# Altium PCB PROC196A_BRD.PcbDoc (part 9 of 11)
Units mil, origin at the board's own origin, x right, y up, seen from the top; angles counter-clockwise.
Board outline 3346.45 x 4921.26 mil, 8 copper layers (Top Layer, GND1, SIG1, PWR1, PWR2, SIG2, GND2, Bottom Layer), stack 54.534 mil thick; 736 components, 498 nets, 3030 pads, 1279 vias.
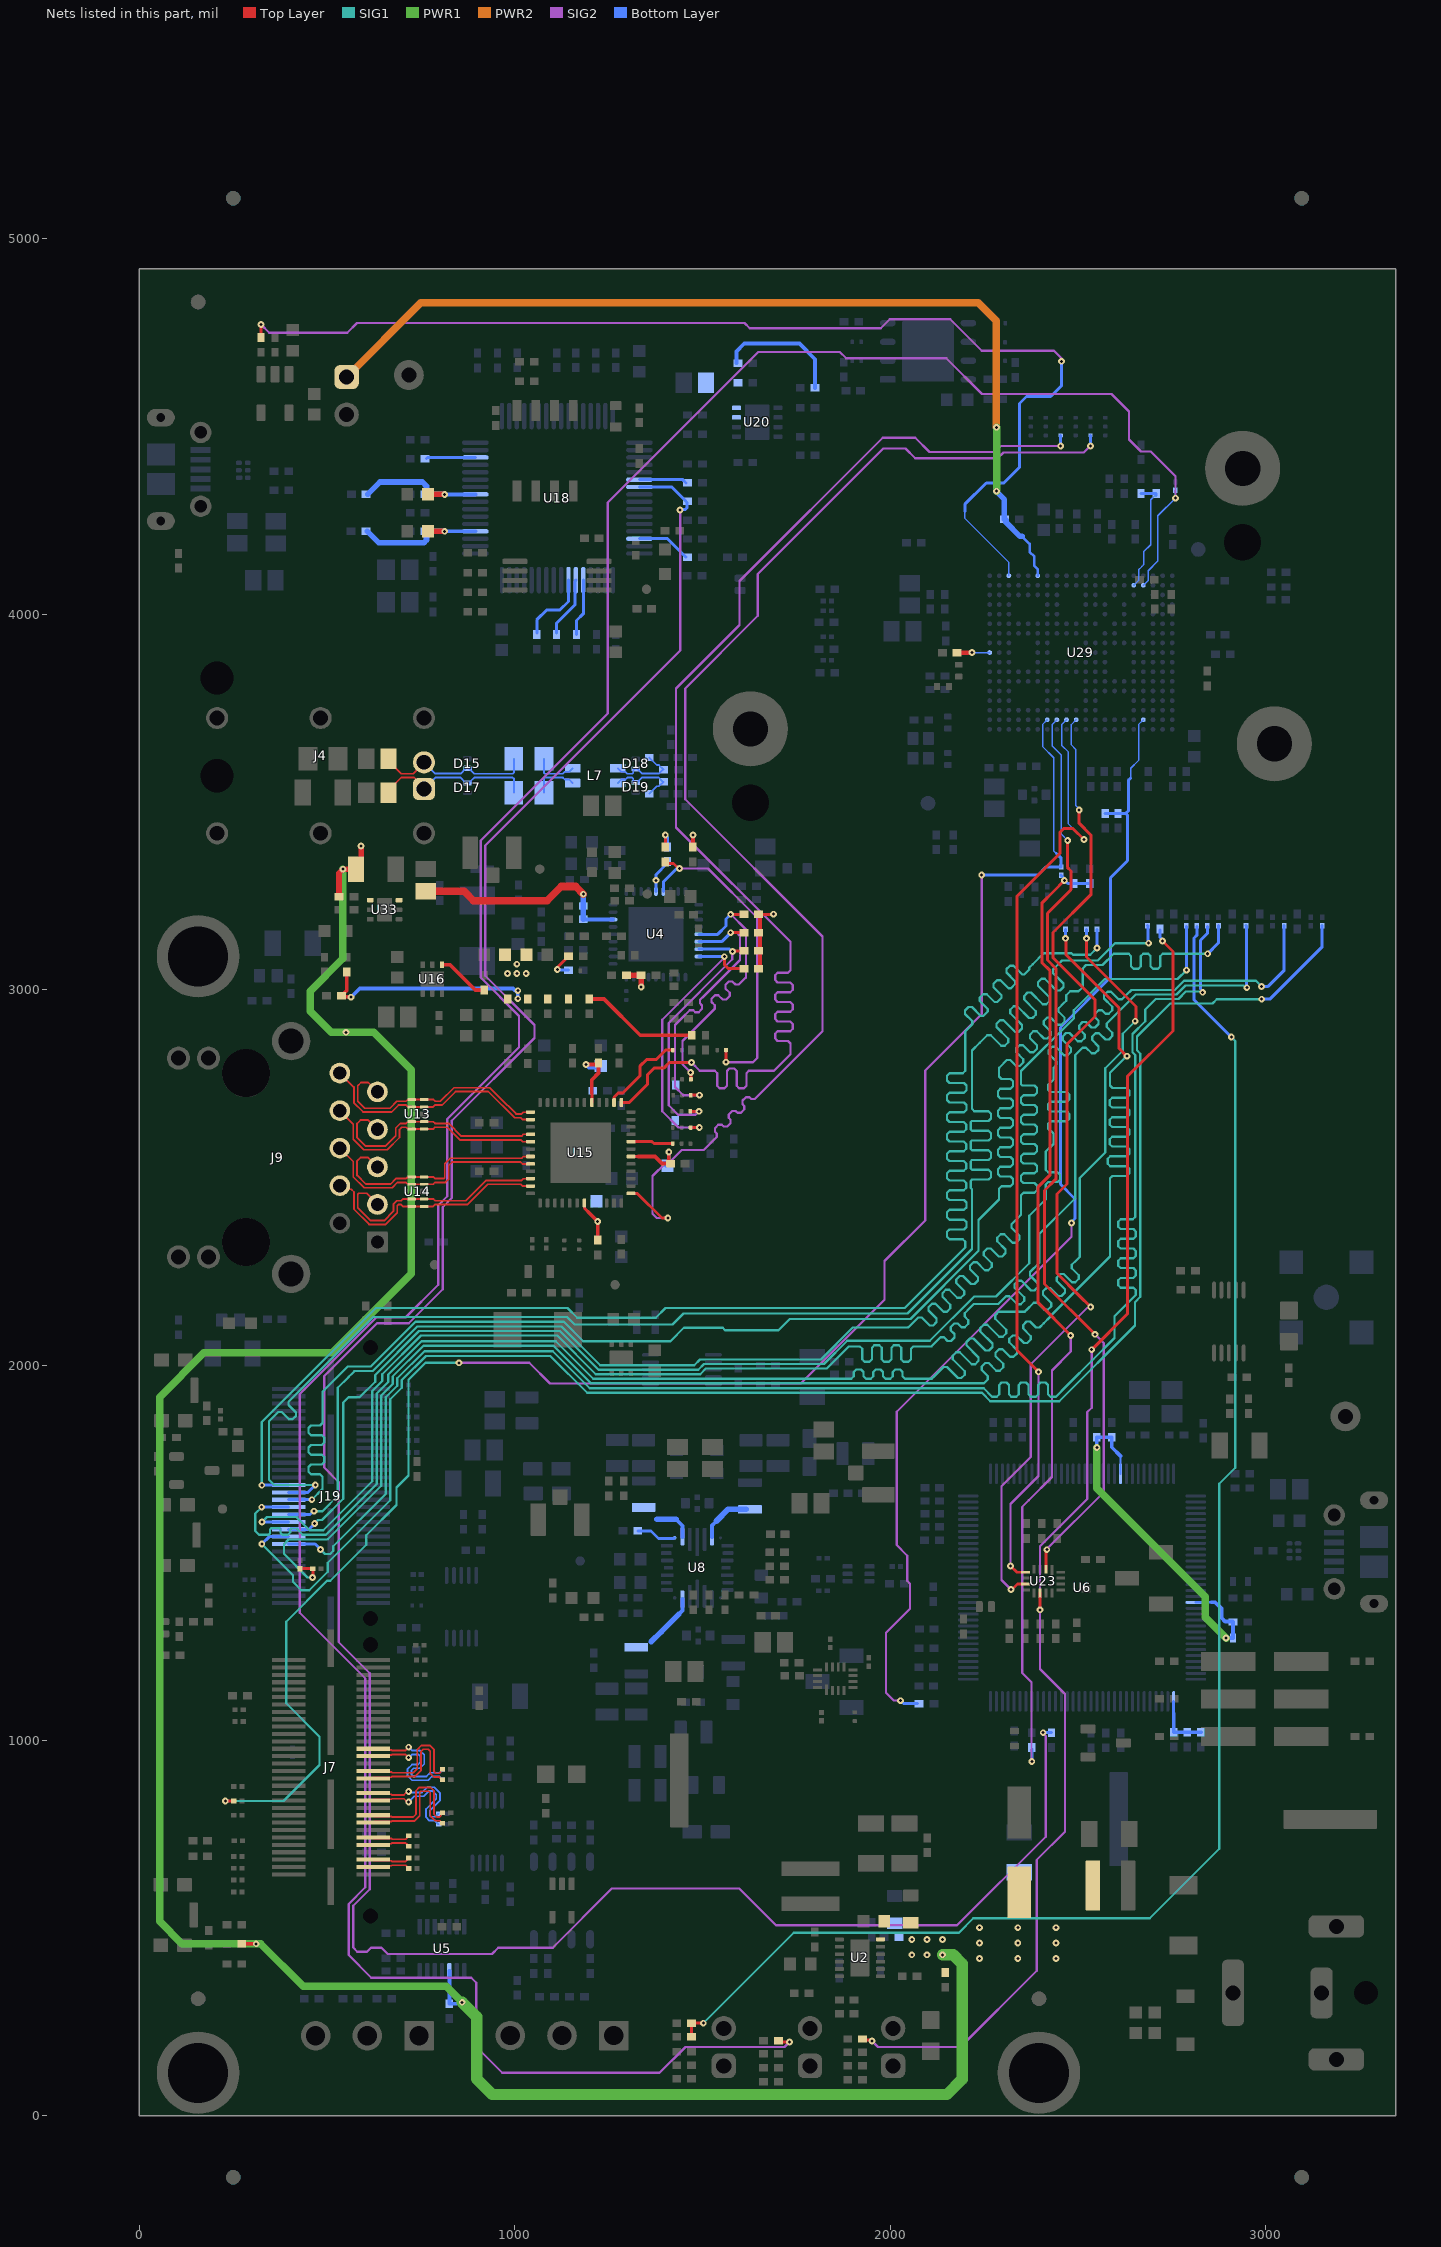
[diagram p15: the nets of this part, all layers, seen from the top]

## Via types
v1: diameter 18, hole 8, Top Layer to Bottom Layer, tented both sides, 1230 vias
v2: diameter 19.68, hole 7.87, Top Layer to Bottom Layer, 30 vias
v3: diameter 20, hole 10, Top Layer to Bottom Layer, tented both sides, 11 vias
v4: diameter 10, hole 4, SIG2 to Bottom Layer, tented both sides, 6 vias
v5: diameter 19.68, hole 7.87, Top Layer to Bottom Layer, tented both sides, 2 vias

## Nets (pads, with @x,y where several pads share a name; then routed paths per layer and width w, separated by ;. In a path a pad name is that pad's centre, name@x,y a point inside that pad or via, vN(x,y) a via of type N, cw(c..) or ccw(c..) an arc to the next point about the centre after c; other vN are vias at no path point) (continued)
RGMII_TD3: R122.2 U15.25 | length 3484.7
  Top Layer w8: U15.25@1309.79,2457.27 1326.6,2457.27 1392.29,2391.59 v1(1407.8,2391.59)
  SIG2 w6: v1(1407.8,2391.59) 1378.54,2391.59 1367,2403.13 1367,2503.47 1402.72,2539.19 1411.26,2539.19 1444.88,2572.81 1503.28,2572.81 1533.64,2603.17 1538.24,2607.77 1538.24,2616.96 1533.29,2621.91 1533.29,2631.1 1542.48,2640.29 1551.67,2640.29 1556.62,2635.34 1565.81,2635.34 1575.01,2644.53 1575.01,2653.73 1570.06,2658.68 1570.06,2667.87 1579.25,2677.06 1588.44,2677.06 1593.39,2672.11 1602.58,2672.11 1611.78,2681.3 1611.78,2690.5 1606.83,2695.45 1606.83,2704.64 1616.02,2713.83 1625.21,2713.83 1630.16,2708.88 1639.35,2708.88 1653.14,2722.67 1671.53,2741.06 1820,2889.53 1820,3141.76 1454.28,3507.48 1454.28,3802.59 1647.68,3995.99 1647.68,4107.4 1982.09,4441.81 2040.97,4441.81 2066.97,4415.81 2286.92,4415.81 2302.11,4431 2515.96,4431 v1(2533.79,4448.83)
  Bottom Layer w8: v1(2533.79,4448.83) R122.2@2533.81,4476.69
RST_FTDI: R163.2 U18.14 | length 131.3
  Bottom Layer w8: R163.2@765.07,4415.03 767.99,4417.95 U18.14@895.17,4417.95
RX_CLK: R290.2 U15.32 | length 113.2
  Top Layer w8: U15.32@1309.79,2595.07 1365.91,2595.07 1370.95,2590.02 R290.2@1420.91,2590.02
RX_CTRL: R195.2 U15.38 | length 238.1
  Top Layer w8: U15.38@1264.51,2699.4 1264.51,2713.47 1275.25,2724.21 1287.3,2724.21 1334.33,2771.24 1334.33,2797.14 1351.5,2814.31 1377.16,2814.31 1402.14,2839.29 R195.2@1421.22,2839.29
RX_D0: R237.2 R255.1 U4.26 | length 761.8
  Top Layer w8: R237.2@1468.46,2632.81 v1@1491.75,2632.81 ; v1(1558.39,3087.85) 1558.39,3067.08 1569.42,3056.06 R255.1@1606.4,3056.06
  SIG2 w6: v1(1491.81,2632.87) 1436.44,2632.87 1393,2676.31 1393,2919.99 1558.39,3085.38 v1(1558.39,3087.85)
  Bottom Layer w8: U4.26@1490.38,3088.51 1490.71,3088.18 1558.06,3088.18 v1(1558.39,3087.85)
RX_D1: R238.2 R256.1 U4.25 | length 718.2
  Top Layer w8: R238.2@1467.74,2676.12 v1@1491.02,2676.12 ; v1(1580.45,3102.05) 1581.4,3102.99 1605.45,3102.99 R256.1@1606.4,3103.94
  SIG2 w6: v1(1491.09,2676.19) 1490.62,2676.19 1481.57,2667.14 1435.17,2667.14 1410,2692.31 1410,2911.64 1579.4,3081.05 1579.4,3101 v1(1580.45,3102.05)
  Bottom Layer w8: U4.25@1490.38,3108.19 1571.68,3108.19 1577.83,3102.05 v1(1580.45,3102.05)
RX_D2: R239.2 R257.1 U4.24 | length 754.5
  Top Layer w8: R239.2@1469.18,2718.89 v1@1492.46,2718.89 ; v1(1575.37,3151.97) R257.1@1606.4,3151.97
  SIG2 w6: v1@1490.08,2716.5 v1@1491.5,2715.07 ; v1(1492.53,2718.95) 1448.86,2718.95 1427,2740.81 1427,2906.27 1445.58,2924.85 1466.08,2945.36 1475.28,2945.36 1480.79,2939.84 1489.98,2939.84 1499.18,2949.03 1499.18,2958.23 1493.66,2963.74 1493.66,2972.94 1504.1,2983.38 1599.88,3079.15 1599.88,3099.89 1599.94,3099.94 1599.94,3114.85 1599.88,3114.91 1599.88,3143.32 1591.23,3151.97 v1(1575.37,3151.97)
  Bottom Layer w8: U4.24@1490.38,3127.88 1551.28,3127.88 v1(1575.37,3151.97)
RX_D3: R240.2 R258.1 U4.23 | length 763
  Top Layer w8: v1(1468.78,2779.77) 1469.11,2779.43 1469.11,2761.42 R240.2@1469.44,2761.09 ; v1(1575.37,3200.99) R258.1@1606.4,3200.99
  SIG2 w6: v1(1468.78,2779.77) 1447,2801.54 1447,2863.63 1530.56,2947.19 1532.69,2949.31 1532.69,2958.5 1524.11,2967.08 1524.11,2976.27 1533.3,2985.47 1542.49,2985.47 1554.12,2973.84 1563.31,2973.84 1572.5,2983.03 1572.5,2992.23 1561.18,3003.55 1561.18,3012.74 1570.37,3021.94 1579.56,3021.94 1587.84,3013.66 1597.03,3013.66 1610.34,3026.97 1616.03,3032.65 1616.03,3160.33 v1(1575.37,3200.99)
  Bottom Layer w8: U4.23@1490.38,3147.56 1540.71,3147.56 1563.06,3169.91 1563.06,3188.68 v1(1575.37,3200.99)
RX_DV: R245.2 R252.1 U4.15 | length 881.8
  Top Layer w8: R245.2@1562.84,2839.29 1562.91,2839.22 1562.91,2806.93 v1(1562.98,2806.86)
  Top Layer w8.3: R252.1@1401.29,3336.43 1422.79,3336.43 1431.14,3328.08 1431.52,3328.08 1436.37,3323.23 v1(1438.99,3323.23)
  SIG2 w6: v1(1438.99,3323.23) 1514.6,3323.23 1645.84,3191.98 1645.84,2817.95 1634.75,2806.86 v1(1562.98,2806.86)
  Bottom Layer w8: U4.15@1395.89,3261.74 1395.89,3287.15 1430.11,3321.37 1437.14,3321.37 v1(1438.99,3323.23)
SOP0_FTDI: R171.1 U18.55 | length 196.5
  Bottom Layer w8: R171.1@1058.91,3950.19 1058.91,3985.33 1085.16,4011.58 1120.24,4011.58 1143.2,4034.54 U18.55@1143.2,4091.18
SOP0_TDO: R310.1 R386.1 U23.10 | length 3595
  Top Layer w7.5: v1(2399.49,1347.9) 2399.58,1347.99 2399.58,1392.88 U23.10@2399.67,1392.97
  Top Layer w8: R310.1@1926.71,204.71 1929.95,201.47 1949.76,201.47 v1(1951.68,199.56) ; v1(2537.07,2041) 2631.98,2135.91 2631.98,2768.53 2753.55,2890.1 2753.55,3101.75 v1(2725.49,3129.81)
  SIG2 w6: v1(1951.68,199.56) 1967.92,183.32 2187.81,183.32 2391,386.5 2391,681.81 2466,756.81 2466,1010.67 2466,1123.92 2399.49,1190.43 v1(2399.49,1347.9) 2399.49,1517.37 2521.93,1639.81 2525.28,1643.16 2525.28,1874.69 2537.07,1886.48 v1(2537.07,2041)
  Bottom Layer w8: R386.1@2719,3159.44 2719,3139.55 2725.49,3133.06 v1(2725.49,3129.81)
SOP1_FTDI: R170.1 U18.54 | length 162.4
  Bottom Layer w8: R170.1@1111.12,3950.19 1111.12,3976.45 1161.12,4026.45 1161.12,4089.42 U18.54@1162.88,4091.18
SOP1_MSS_SPIB_CS2: R305.1 R324.1 U29.T17 | length 8106.6
  Top Layer w8: R305.1@1702.27,199.99 1705.42,196.84 v1(1732.2,196.84)
  SIG2 w6: v1(1732.2,196.84) 1718.96,183.59 1454.95,183.59 1385.92,114.56 966.81,114.56 897.44,183.93 897.44,354.61 884.24,367.81 635.39,367.81 620.47,367.8 618,367.81 557.53,428.28 557.53,564.31 602,608.78 602,1165.35 427,1340.35 427,1922.73 631.22,2126.96 709.25,2126.96 796,2213.71 796,2425.37 820.24,2449.61 820.24,2655.8 1011.33,2846.89 1011.33,2930.27 909.28,3032.32 909.28,3397.28 1248,3736 1248,4297.94 1648.92,4698.86 1866,4698.86 1882.86,4682 2149.53,4682 2244.72,4586.81 2590,4586.81 2636.5,4540.31 2636.5,4465.81 2668.5,4433.81 2694.49,4433.81 2760.08,4368.22 v1(2760.08,4309.55)
  Bottom Layer w4: U29.T17@2674.75,4077.38 2687.47,4090.1 2687.47,4097.65 2687.51,4097.69 2687.51,4108.26 2687.47,4108.29 2687.47,4116.03 2713.31,4141.87 2713.31,4262.78 v1(2760.08,4309.55) ; v1@2759.85,4309.55 R324.1@2759.85,4330.39
SOP2_FTDI: R169.1 U18.53 | length 152.4
  Bottom Layer w8: R169.1@1164.49,3946.25 1164.49,3983.49 1182.57,4001.57 U18.53@1182.57,4091.18
SOP2_PMIC_CLK: R218.2 R297.1 R299.1 | length 4157.5
  Top Layer w8: R299.1@1471.02,210.44 R297.1@1471.02,246.66 v1(1502.46,246.66)
  SIG1 w6: v1(1502.46,246.66) 1743.64,487.84 2161.97,487.84 ; 2162,487.81 2183.47,487.81 2221.84,526.18 2691.83,526.18 2877.17,711.52 2877.17,1684.09 2919.5,1726.43 2919.5,2863.31 v1(2909,2873.81)
  Bottom Layer w8: R218.2@2817.15,3168.1 2817.15,3144.83 2809.82,3137.5 2809.82,2972.99 v1(2909,2873.81)
SOP3_MSS_GPIO_0: R212.1 R328.1 U29.B7 | length 4795.3
  Top Layer w8: v1(229,838.88) R328.1@251.34,838.88
  SIG1 w6: v1(229,838.88) 384.07,838.88 480,934.81 480,1009.81 391,1098.81 391,1316.13 500.1,1425.23 508.47,1425.23 604.23,1521 604.23,1546.36 685,1627.13 685,1674.12 716.99,1706.11 716.99,1960.77 762.17,2005.95 v1(851.82,2005.95)
  SIG2 w6: v1(851.82,2005.95) 1038.71,2005.95 1093.86,1950.8 1761.77,1950.8 1985.17,2174.2 1985.17,2276.96 2093.57,2385.36 2093.57,2784.84 2244,2935.27 2244,3261.81 v1(2244,3305.81)
  Bottom Layer w4: U29.B7@2418.84,3719.11 2406.12,3706.39 2406.12,3648.17 2436.13,3618.17 2436.13,3369.86 2443.6,3362.38
  Bottom Layer w8: v1(2244,3305.81) 2393.75,3305.81 2414.98,3327.04 R212.1@2455.7,3327.04 2455.7,3350.29 2443.6,3362.38
SOP3_MSS_UARTB_TX: R136.1 R212.2 R301.1 R303.2 | length 2616.2
  Top Layer w8: v1(2464.23,3290.81) 2435.23,3261.81 2404.11,3230.69 2404.11,3072.71 2426.4,3050.43 2426.4,2506.84 2394.34,2474.78 2394.34,2165.75 v1(2481.09,2079)
  SIG2 w6: v1(2377.63,944.16) 2376.98,944.8 2376.98,1154.83 2351.93,1179.88 2351.93,1389.31 2352,1389.38 2352,1414.24 2351.93,1414.31 2351.93,1622.23 2369.5,1639.81 2431.31,1701.61 2431.31,1985.73 2481.51,2035.93 2481.51,2078.58 v1(2481.09,2079)
  Bottom Layer w8: v1(2377.63,944.16) R136.1@2377.63,977.32 ; R212.2@2455.7,3304.99 2455.7,3304.21 2461.93,3297.97 2461.93,3293.11 v1(2464.23,3290.81) 2465.36,3290.81 2473.29,3282.88 R303.2@2489.92,3282.88 R301.1@2531.76,3282.88
SOP4_MSS_UARTA_TX: R128.1 R309.1 R312.2 U29.B17 | length 3093.3
  SIG2 w6: v1(2027.55,1106) 2026.86,1106.69 2009.55,1106.69 1989.24,1127 1989.24,1286.82 2053.08,1350.66 2053.08,1417.7 2045.5,1425.28 2045.5,1492.31 2017.44,1520.37 2017.44,1875.83 2483.45,2341.84 v1(2483.45,2378.67)
  Bottom Layer w4: 2641,3564.31 2641,3589.81 2661.92,3610.73 2661.92,3658.75 2661.92,3661.86 2661.92,3706.28 U29.B17@2674.75,3719.11
  Bottom Layer w8: v1(2027.55,1106) 2029.03,1106 2037.24,1097.79 R128.1@2073.35,1097.79 ; v1(2483.45,2378.67) 2483.45,2381.38 2492.87,2390.8 2492.87,2442.65 2453.66,2481.86 2453.66,2899.47 2587.2,3033.01 2587.2,3261.81 2587.2,3298.15 2625,3335.95 2632.69,3343.64 2632.69,3465.12 2628,3469.81 ; R312.2@2572.88,3469.81 R309.1@2607.16,3469.81 2628,3469.81 ; 2641,3564.31 2634.5,3557.81 2634.5,3476.31 2628,3469.81
SPIB_CS1/SPI_HOST_IRQ: R107.2 R109.2 U29.T16 | length 311.5
  Bottom Layer w4: U29.T16@2649.16,4077.38 2661.92,4090.14 2661.92,4118.66 2670.96,4127.7 2675.3,4132.04 2675.3,4138.07 2675.3,4166.54 2694.31,4185.55 2694.31,4305.07 2706.05,4316.81 R107.2@2709,4316.81
  Bottom Layer w8: R109.2@2668.4,4321.73 R107.2@2709,4321.73 R107.2@2709,4316.81
STRP_1: R253.1 U4.14 | length 88.4
  Bottom Layer w8: U4.14@1376.2,3261.74 v1(1376.2,3291.35) 1376.2,3306.53 R253.1@1407.02,3337.34
SW_B1: L9.1 U8.28 | length 139.3
  Bottom Layer w10: U8.28@1525.61,1541.88 1525.61,1572.9 1536.74,1584.03
  Bottom Layer w15: 1536.74,1584.03 1568.8,1616.1 L9.1@1615.99,1616.1
SW_B2: L8.1 U8.24 | length 105
  Bottom Layer w10: 1429.51,1589.3 1446.87,1571.93 U8.24@1446.87,1541.88
  Bottom Layer w15: 1379.14,1589.3 1429.51,1589.3
SW_B3: L2.1 U8.14 | length 148
  Bottom Layer w10: 1437.44,1336.49 1446.76,1345.81 U8.14@1446.76,1376.58
  Bottom Layer w15: 1363.72,1263.14 1389.23,1288.65 1389.6,1288.65 1437.44,1336.49
SYNCCLKIN: R75.2 U8.23 | length 107
  Bottom Layer w8: R75.2@1327.76,1558.22 1363.12,1558.22 1383.16,1538.18 1424.43,1538.18 U8.23@1425.9,1539.66
TCK: U23.2 U29.B8 | length 2466.7
  Top Layer w7.5: U23.2@2415.42,1455.96 2415.42,1467.77 2415.56,1467.92 2415.56,1506.24 v1(2417.49,1508.18)
  Top Layer w8: v1(2473,3397.81) 2471.96,3396.77 2471.96,3326.44 2482.23,3316.17 2482.23,3266.49 2477.55,3261.81 2419.11,3203.37 2419.11,3078.93 2441.4,3056.64 2441.4,2494.96 2411.47,2465.03 2411.47,2216.11 v1(2545.59,2081.99)
  SIG2 w6: v1(2417.49,1508.18) 2417.49,1509.92 2568.86,1661.28 2568.86,2058.73 v1(2545.59,2081.99)
  Bottom Layer w4: U29.B8@2444.43,3719.11 2431.71,3706.39 2431.71,3649.45 2456.04,3625.12 2456.04,3414.77 v1(2473,3397.81)
TD_1_N: J9.10 U13.2 U13.9 U15.2 | length 633
  Top Layer w4.8: J9.10@534.18,2777.93 571.46,2740.65 571.46,2698.61 595.93,2674.14 671.99,2674.14 690.38,2692.53 710.31,2692.53 713.52,2689.33 724.1,2689.33 U13.2@725.63,2687.79 U13.9@758.51,2687.79 782.36,2687.79 787.1,2692.53 787.92,2692.53 788,2692.61 806.23,2692.61 842.43,2728.81 929.58,2728.81 999.52,2658.87 1016.22,2658.87 1020.96,2654.12 U15.2@1042.07,2654.12
TD_1_P: J9.9 U13.1 U13.10 U15.1 | length 633.2
  Top Layer w4.8: J9.9@634.18,2727.93 609.3,2752.81 590.43,2752.81 581.66,2744.04 581.66,2702.83 600.15,2684.34 667.76,2684.34 686.15,2702.73 710.31,2702.73 713.52,2705.94 724.1,2705.94 U13.1@725.63,2707.48 U13.10@758.51,2707.48 782.36,2707.48 783.26,2707.48 787.92,2702.81 802,2702.81 838.2,2739.01 933.8,2739.01 957.78,2715.04 959,2713.81 1003.74,2669.07 1018.29,2669.07 1023.03,2673.81 U15.1@1042.07,2673.81
TD_2_N: J9.8 U13.5 U13.6 U15.5 | length 631
  Top Layer w4.8: J9.8@534.18,2677.93 569.96,2642.14 569.96,2601.42 597.78,2573.61 660.23,2573.61 693,2606.39 693,2627.31 699.17,2633.48 710.31,2633.48 713.52,2630.27 724.1,2630.27 U13.5@725.63,2628.74 U13.6@758.51,2628.74 782.36,2628.74 787.1,2633.48 ; 788,2633.56 819.83,2633.56 827.79,2625.6 853.57,2599.81 1016.22,2599.81 1020.96,2595.07 U15.5@1042.07,2595.07
TD_2_P: J9.7 U13.4 U13.7 U15.4 | length 633
  Top Layer w4.8: J9.7@634.18,2627.93 609.4,2652.71 589.21,2652.71 580.16,2643.67 580.16,2605.65 602,2583.81 656,2583.81 682.8,2610.61 682.8,2631.54 694.94,2643.68 710.31,2643.68 713.52,2646.88 724.1,2646.88 U13.4@725.63,2648.42 U13.7@758.51,2648.42 782.36,2648.42 ; 783.26,2648.42 787.92,2643.76 824.06,2643.76 857.8,2610.01 1018.29,2610.01 1023.03,2614.75 U15.4@1042.07,2614.75
TD_3_N: J9.6 U14.2 U14.9 U15.8 | length 630.4
  Top Layer w4.8: J9.6@534.18,2577.93 568.47,2543.64 569.96,2542.14 569.96,2501.08 598.79,2472.26 673.37,2472.26 687.57,2486.46 710.31,2486.46 713.52,2483.26 724.1,2483.26 U14.2@725.63,2481.72 U14.9@758.51,2481.72 782.36,2481.72 787.1,2486.46 ; 788,2486.54 815.21,2486.54 824,2495.32 824,2531.81 832.95,2540.76 1016.22,2540.76 1020.96,2536.01 U15.8@1042.07,2536.01
TD_3_P: J9.5 U14.1 U14.10 U15.7 | length 632.4
  Top Layer w4.8: J9.5@634.18,2527.93 609.4,2552.71 589.21,2552.71 583.05,2546.55 580.16,2543.67 580.16,2505.31 603.01,2482.46 669.14,2482.46 683.35,2496.66 710.31,2496.66 713.52,2499.87 724.1,2499.87 U14.1@725.63,2501.4 U14.10@758.51,2501.4 782.36,2501.4 ; 783.26,2501.4 787.92,2496.74 810.99,2496.74 813.8,2499.55 813.8,2536.04 828.72,2550.96 1018.29,2550.96 1023.03,2555.7 U15.7@1042.07,2555.7
TD_4_N: J9.4 U14.5 U14.6 U15.11 | length 638
  Top Layer w4.8: J9.4@534.18,2477.93 543.52,2468.58 564.38,2468.58 571.8,2461.17 571.8,2414.98 611.92,2374.86 656.14,2374.86 686.92,2405.64 686.92,2424.59 689.73,2427.41 697.29,2427.41 702.03,2422.66 U14.5@725.63,2422.66 U14.6@758.51,2422.66 782.36,2422.66 787.1,2427.41 ; 788,2427.48 873.67,2427.48 927.89,2481.7 1016.22,2481.7 1020.96,2476.96 U15.11@1042.07,2476.96
TD_4_P: J9.3 U14.4 U14.7 U15.10 | length 629.5
  Top Layer w4.8: J9.3@630,2432.81 605.22,2457.59 584.81,2457.59 582,2454.78 582,2419.21 616.14,2385.06 651.92,2385.06 676.72,2409.87 676.72,2428.82 685.51,2437.61 697.29,2437.61 702.03,2442.35 U14.4@725.63,2442.35 U14.7@758.51,2442.35 782.36,2442.35 ; 783.26,2442.35 787.92,2437.68 869.45,2437.68 923.67,2491.9 1018.29,2491.9 1023.03,2496.64 U15.10@1042.07,2496.64
TDI: U23.5 U29.B9 | length 2531.8
  Top Layer w7.5: v1(2321,1464.81) 2337.72,1448.09 U23.5@2360.3,1448.09
  Top Layer w8: v1(2395.4,1982) 2338.62,2038.78 2338.62,3249.85 2350.58,3261.81 2453.23,3364.46 2453.23,3420 2462.23,3429 2487.55,3429 2516.64,3399.91 v1(2516.78,3399.91)
  SIG2 w6: v1(2321,1464.81) 2321,1629.82 2395.4,1704.22 v1(2395.4,1982)
  Bottom Layer w4: 2457.2,3706.28 U29.B9@2470.03,3719.11 ; 2457.3,3706.39 2457.3,3650.73 2475.13,3632.91 2475.13,3441.56 v1(2516.78,3399.91)
TMS: U23.7 U29.B10 | length 2668.7
  Top Layer w7.5: v1(2322,1401.81) 2324.4,1401.81 2339.19,1416.59 U23.7@2360.3,1416.59
  Top Layer w8: v1(2503.79,3479) 2503.67,3478.88 2503.67,3443.14 2534.78,3412.03 2534.78,3330.05 2534.72,3329.98 2534.72,3315.07 2534.78,3315.01 2534.78,3261.81 2534.78,3252.85 2434.11,3152.18 2434.11,3085.14 2545.64,2973.61 2545.64,2928.93 2471.49,2854.78 2471.49,2482.63 2444.42,2455.55 2444.42,2244.59 2502.73,2186.28 v1(2534.32,2154.69)
  SIG2 w6: v1(2322,1401.81) 2296.64,1427.17 2296.64,1677 2375,1755.36 2375,2001.97 2525.42,2152.39 2532.03,2152.39 v1(2534.32,2154.69)
  Bottom Layer w4: 2482.79,3706.28 2482.89,3706.39 ; U29.B10@2495.62,3719.11 2482.89,3706.39 ; v1(2503.79,3479) 2503.79,3481.98 2494.67,3491.1 2494.67,3640.23 2482.89,3652.01 2482.89,3706.39
TRACE_CLK: R72.1 R216.2 R226.1 | length 4614.9
  Top Layer w8: R72.1@427.98,1457.52 440.56,1457.52 440.66,1457.42 R226.1@461.96,1457.42 461.96,1435.33 v1(460.97,1434.35) ; v1(2467.11,3136.81) 2468.67,3135.26 2468.67,3093.01 2609.94,2951.74 2609.94,2843.86 v1(2630.8,2823)
  SIG1 w6: v1(460.97,1434.35) 447.89,1434.35 384.99,1497.25 384.99,1522.93 397.16,1535.1 500.85,1535.1 501.73,1535.98 501.9,1535.98 644.42,1678.5 644.42,1919.03 675.2,1949.81 675.2,1969.89 756.82,2051.52 1103.5,2051.52 1203.21,1951.81 2250,1951.81 2258,1959.81 2260.12,1961.93 2260.12,1971.12 2244.16,1987.09 2244.16,1996.28 2253.35,2005.47 2262.54,2005.47 2282.88,1985.14 2292.07,1985.14 2301.26,1994.33 2301.26,2003.52 2280.93,2023.86 2280.93,2033.05 2290.12,2042.24 2299.31,2042.24 2319.65,2021.91 2328.84,2021.91 2338.03,2031.1 2338.03,2040.29 2317.7,2060.63 2317.7,2069.82 2326.89,2079.01 2336.08,2079.01 2356.42,2058.68 2365.61,2058.68 2374.8,2067.87 2374.8,2077.06 2354.47,2097.4 2354.47,2106.59 2363.66,2115.78 2372.85,2115.78 2388.82,2099.82 2398.01,2099.82 2409.5,2111.31 2426,2127.81 2426,2129.18 2586,2289.18 2586,2468.5 2586,2497.5 2592.5,2504 2630.95,2504 2637.45,2510.5 2637.45,2523.5 2630.95,2530 2586.66,2530 2580.16,2536.5 2580.16,2549.5 2586.66,2556 2630.95,2556 2637.45,2562.5 2637.45,2575.5 2630.95,2582 2591.5,2582 2585,2588.5 2585,2601.5 2591.5,2608 2630.95,2608 2637.45,2614.5 2637.45,2627.5 2630.95,2634 2591.5,2634 2585,2640.5 2585,2653.5 2591.5,2660 2630.95,2660 2637.45,2666.5 2637.45,2679.5 2630.95,2686 2591.5,2686 2585,2692.5 2585,2705.5 2591.5,2712 2630.95,2712 2637.45,2718.5 2637.45,2731.5 2630.95,2738 2592.5,2738 2586,2744.5 2586,2760.81 2586,2778.97 2630.03,2823 v1(2630.8,2823)
  Bottom Layer w8: R216.2@2467,3160.76 2467.06,3160.71 2467.06,3136.87 v1(2467.11,3136.81)
TRACE_CTL: J19.17 R220.2 | length 4486.7
  SIG1 w6: v1(482.54,1508.92) 494.46,1497 508.73,1497 516.81,1505.08 516.81,1517.06 656.42,1656.67 656.42,1914.06 687.2,1944.84 687.2,1964.92 759.31,2037.03 1101.02,2037.03 1199.94,1938.11 2249.49,1938.11 2271.78,1915.82 2281,1915.82 2284,1915.82 2290.5,1922.32 2290.5,1947.12 2297,1953.62 2310,1953.62 2316.5,1947.12 2316.5,1922.32 2323,1915.82 2336,1915.82 2342.5,1922.32 2342.5,1947.12 2349,1953.62 2362,1953.62 2368.5,1947.12 2368.5,1922.32 2375,1915.82 2388,1915.82 2394.5,1922.32 2394.5,1947.12 2401,1953.62 2414,1953.62 2420.5,1947.12 2420.5,1922.32 2427,1915.82 2442,1915.82 ; 2442.01,1915.82 2471.5,1945.31 2541.5,2015.31 2598.1,2071.91 2598.1,2130.21 2654.7,2186.81 2654.7,2199.81 2648.2,2206.31 2614.47,2206.31 2607.97,2212.81 2607.97,2225.81 2614.47,2232.31 2648.2,2232.31 2654.7,2238.81 2654.7,2251.81 2648.2,2258.31 2614.47,2258.31 2607.97,2264.81 2607.97,2277.81 2614.47,2284.31 2648.2,2284.31 2654.7,2290.81 2654.7,2303.81 2648.2,2310.31 2614.47,2310.31 2607.97,2316.81 2607.97,2329.81 2614.47,2336.31 2648.2,2336.31 2654.7,2342.81 2654.7,2355.81 2648.2,2362.31 2614.47,2362.31 2607.97,2368.81 2607.97,2381.81 2614.47,2388.31 2646.5,2388.31 2653,2394.81 2653,2411.81 2653,2826.26 2645.74,2833.52 2645.74,2882.05 2680,2916.31 2680,2947.45 2708.06,2975.51 2768.19,2975.51 2787.78,2995.1 2830.78,2995.1 v1(2832.88,2993)
  Bottom Layer w8: J19.17@397.49,1523.18 468.28,1523.18 v1(482.54,1508.92) ; v1(2832.88,2993) 2832.88,2995.71 2826.82,3001.77 2826.82,3131.45 2845,3149.63 R220.2@2845,3168.1
TRACE_DATA0: J19.19 R227.1 | length 4470.6
  SIG1 w6: v1(326.24,1523.18) 409,1440.42 409,1422.52 431.52,1400 452.3,1400 502.04,1449.74 502.04,1473.34 668.42,1639.72 668.42,1909.09 699.2,1939.87 699.2,1959.95 763.51,2024.27 1094.75,2024.27 1192.91,1926.11 2244.52,1926.11 2266.81,1903.82 2450.62,1903.82 2652.47,2105.66 2652.47,2167.61 2666.7,2181.84 2666.7,2829.53 2657.74,2838.49 2657.74,2875.18 2746.07,2963.51 2859.07,2963.51 2870.37,2974.81 2876.92,2974.81 2920.47,2974.81 v1(2990,2974.81)
  Bottom Layer w8: v1(326.24,1523.18) 345.93,1542.86 J19.19@397.49,1542.86 ; v1(2990,2974.81) 3011.7,2974.81 3151,3114.11 R227.1@3151,3170.76
TRACE_DATA1: J19.21 R231.1 | length 4488.3
  SIG1 w6: v1(466.95,1577.98) 475.97,1587 486.71,1587 543.27,1643.56 543.27,1900.01 557.26,1914 586.53,1914 628.25,1955.72 628.25,1973.86 745.05,2090.65 1120.19,2090.65 1223.03,1987.81 1489,1987.81 1504.19,2003 1824,2003 1885.54,2064.54 2105.73,2064.54 2224,2182.81 2282.2,2182.81 2371,2271.62 2371,2397.76 2415,2441.76 2415,2452 2415,2481 2421.5,2487.5 2446.01,2487.5 2452.51,2494 2452.51,2507 2446.01,2513.5 2421.5,2513.5 2415,2520 2415,2531 2415,2569.15 2435.07,2589.23 2435.07,2613.81 2435.07,2616.81 2428.57,2623.31 2427.26,2623.31 2420.76,2629.81 2420.76,2642.81 2427.26,2649.31 2470.97,2649.31 2477.47,2655.81 2477.47,2668.81 2470.97,2675.31 2427.26,2675.31 2420.76,2681.81 2420.76,2694.81 2427.26,2701.31 2470.97,2701.31 2477.47,2707.81 2477.47,2720.81 2470.97,2727.31 2427.26,2727.31 2420.76,2733.81 2420.76,2746.81 2427.26,2753.31 2428.57,2753.31 2435.07,2759.81 2435.07,2780.81 2435.07,2791.74 2441.07,2797.74 2443.19,2799.86 2443.19,2809.05 2422.91,2829.34 2422.91,2838.53 2432.1,2847.72 2441.29,2847.72 2463.33,2825.69 2472.52,2825.69 2481.71,2834.88 2481.71,2844.07 2459.68,2866.11 2459.68,2875.3 2468.87,2884.49 2478.06,2884.49 2500.1,2862.46 2509.29,2862.46 2518.48,2871.65 2518.48,2880.84 2503.63,2895.7 2503.63,2904.89 2512.82,2914.08 2522.01,2914.08 2536.86,2899.23 2546.06,2899.23 2555.25,2908.42 2555.25,2917.61 2545.95,2926.91 2545.95,2936.1 2555.15,2945.29 2564.34,2945.29 2573.63,2936 2582.83,2936 2592.02,2945.19 2592.02,2954.38 2569.98,2976.42 2569.98,2985.61 2579.18,2994.8 2588.37,2994.8 2608.66,2974.51 2617.85,2974.51 2630.57,2987.24 2642.84,2999.51 2758.25,2999.51 2782.83,3024.09 2974.51,3024.09 v1(2989.7,3008.89)
  Bottom Layer w8: J19.21@397.49,1562.55 452.21,1562.55 466.95,1577.28 v1(466.95,1577.98) ; v1(2989.7,3008.89) 3007.08,3008.89 3050,3051.81 R231.1@3050,3170.76
TRACE_DATA2: J19.23 R235.1 | length 4542.9
  SIG1 w6: v1(327,1581.81) 340.19,1595 418.22,1595 453.24,1559.98 489.6,1559.98 620.42,1690.8 620.42,1930.92 647.1,1957.6 647.1,1975.74 750.02,2078.65 1113.16,2078.65 1216,1975.81 1493.97,1975.81 1509.16,1991 1831.19,1991 1890,2049.81 1919,2049.81 1925.5,2043.31 1925.5,2015.23 1932,2008.73 1945,2008.73 1951.5,2015.23 1951.5,2046.04 1958,2052.54 1971,2052.54 1977.5,2046.04 1977.5,2015.23 1984,2008.73 1997,2008.73 2003.5,2015.23 2003.5,2046.04 2010,2052.54 2023,2052.54 2029.5,2046.04 2029.5,2015.23 2036,2008.73 2049,2008.73 2055.5,2015.23 2055.5,2043.31 2062,2049.81 2103,2049.81 2110,2049.81 2111.26,2051.07 2120.45,2060.26 2134.24,2074.05 2143.43,2074.05 2153.21,2064.27 2162.41,2064.27 2171.6,2073.46 2171.6,2082.65 2161.82,2092.44 2161.82,2101.63 2171.01,2110.82 2180.2,2110.82 2189.98,2101.04 2199.18,2101.04 2208.37,2110.23 2208.37,2119.42 2198.59,2129.21 2198.59,2138.4 2212.38,2152.19 2216,2155.81 2223,2162.81 2288,2162.81 2308.51,2183.32 2317.7,2183.32 2338.84,2162.18 2348.03,2162.18 2357.22,2171.37 2357.22,2180.56 2331.67,2206.12 2331.67,2215.31 2340.86,2224.5 2350.05,2224.5 2375.61,2198.95 2384.8,2198.95 2393.99,2208.14 2393.99,2217.33 2372.85,2238.47 2372.85,2247.66 2398,2272.81 2398,2286.81 2398,2349.64 2493,2444.64 2493,2824.2 2493,2825.81 2512.7,2845.51 2521.89,2845.51 2536.94,2830.47 2546.13,2830.47 2555.32,2839.66 2555.32,2848.85 2538.3,2865.87 2538.3,2875.07 2547.49,2884.26 2556.69,2884.26 2573.71,2867.24 2582.9,2867.24 2592.09,2876.43 2592.09,2885.62 2577.05,2900.67 2577.05,2909.86 2605.85,2938.67 2654.7,2987.51 2763.22,2987.51 2786.73,3011.02 2941.41,3011.02 2947.05,3005.38 v1(2950.3,3005.38)
  Bottom Layer w8: v1(327,1581.81) 327.21,1582.02 397.28,1582.02 J19.23@397.49,1582.23 ; R235.1@2947.88,3170.76 2949.09,3169.55 2949.09,3006.59 v1(2950.3,3005.38)
TRACE_DATA3: J19.25 R217.1 | length 4516
  SIG1 w6: v1(465.04,1610.85) 488.04,1610.85 528.74,1651.55 528.74,1939.45 557.81,1968.52 557.81,1968.6 568.36,1979.14 568.43,1979.14 573.29,1984 621.42,1984 740.43,2103 1124.81,2103 1227.99,1999.82 1478.09,1999.82 1493.27,2015 1816,2015 1900.81,2099.81 2047.99,2099.81 2054.5,2106.31 2075,2126.82 2084.2,2126.82 2105.43,2105.59 2114.62,2105.59 2123.81,2114.78 2123.81,2123.97 2102.58,2145.21 2102.58,2154.4 2111.77,2163.59 2120.96,2163.59 2142.2,2142.36 2151.39,2142.36 2160.58,2151.55 2160.58,2160.74 2139.35,2181.97 2139.35,2191.17 2148.54,2200.36 2157.73,2200.36 2178.97,2179.13 2188.16,2179.13 2197.35,2188.32 2197.35,2197.51 2176.12,2218.74 2176.12,2227.94 2185.31,2237.13 2194.5,2237.13 2215.73,2215.9 2224.93,2215.9 2234.12,2225.09 2234.12,2234.28 2212.89,2255.51 2212.89,2264.71 2222.08,2273.9 2231.27,2273.9 2252.5,2252.67 2261.7,2252.67 2270.89,2261.86 2270.89,2271.05 2249.62,2292.32 2249.62,2301.51 2258.81,2310.71 2268.01,2310.71 2289.27,2289.44 2298.47,2289.44 2307.66,2298.63 2307.66,2307.82 2285.53,2329.95 2285.53,2339.15 2294.72,2348.34 2303.91,2348.34 2326.04,2326.21 2335.24,2326.21 2344.43,2335.4 2344.43,2344.59 2323.2,2365.82 2323.2,2375.02 2344.5,2396.31 2349,2400.82 2349,2419.81 2349,2432.81 2349,2452.31 2355.5,2458.81 2384.75,2458.81 2391.25,2465.31 2391.25,2478.31 2384.75,2484.81 2355.5,2484.81 2349,2491.31 2349,2504.31 2355.5,2510.81 2384.75,2510.81 2391.25,2517.31 2391.25,2530.31 2384.75,2536.81 2355.5,2536.81 2349,2543.31 2349,2556.31 2355.5,2562.81 2384.75,2562.81 2391.25,2569.31 2391.25,2582.31 2384.75,2588.81 2355.5,2588.81 2349,2595.31 2349,2608.31 2355.5,2614.81 2384.75,2614.81 2391.25,2621.31 2391.25,2634.31 2384.75,2640.81 2355.5,2640.81 2349,2647.31 2349,2660.31 2355.5,2666.81 2384.75,2666.81 2391.25,2673.31 2391.25,2686.31 2384.75,2692.81 2355.5,2692.81 2349,2699.31 2349,2712.31 2355.5,2718.81 2384.75,2718.81 2391.25,2725.31 2391.25,2738.31 2384.75,2744.81 2352.19,2744.81 2349,2748 2349,2783.23 2488.94,2923.17 2488.94,2945.57 2571.77,3028.4 2765.77,3028.4 v1(2789.37,3052)
  Bottom Layer w8: J19.25@397.49,1601.92 454.63,1601.92 463.56,1610.85 v1(465.04,1610.85) ; R217.1@2789.3,3168.1 2789.15,3167.95 2789.15,3052.22 v1(2789.37,3052)
TRACE_DATA4: J19.27 R221.1 | length 4624.2
  Top Layer w8: v1(2523,3136.81) 2523,3087.31 2654.89,2955.42 2654.89,2917.91 v1(2652.98,2916)
  SIG1 w6: v1(325.88,1621.47) 308.99,1604.58 308.99,1557.85 318.86,1547.98 344.49,1547.98 348,1551.5 348,1561.75 351.51,1565.26 372.7,1565.26 376.21,1561.75 376.21,1553.15 381.38,1547.98 395.13,1547.98 401.88,1554.73 401.88,1561.44 405.4,1564.96 418.61,1564.96 435.59,1547.98 496.93,1547.98 632.42,1683.47 632.42,1924 663.2,1954.78 663.2,1974.86 751.85,2063.52 1109.29,2063.52 1209,1963.81 1868.53,1963.81 1896.7,1963.81 1903.2,1970.31 1903.2,1981.7 1909.7,1988.2 1922.7,1988.2 1929.2,1981.7 1929.2,1970.31 1935.7,1963.81 1948.7,1963.81 1955.2,1970.31 1955.2,1981.7 1961.7,1988.2 1974.7,1988.2 1981.2,1981.7 1981.2,1970.31 1987.7,1963.81 2000.7,1963.81 2007.2,1970.31 2007.2,1981.7 2013.7,1988.2 2026.7,1988.2 2033.2,1981.7 2033.2,1970.31 2039.7,1963.81 2068.7,1963.81 2111.26,1963.81 2115.71,1968.26 2142.12,1994.67 2151.32,1994.67 2180.65,1965.33 2189.85,1965.33 2199.04,1974.53 2199.04,1983.72 2166.92,2015.83 2166.92,2025.03 2176.12,2034.22 2185.31,2034.22 2217.42,2002.1 2226.62,2002.1 2235.81,2011.3 2235.81,2020.49 2203.69,2052.6 2203.69,2061.8 2212.89,2070.99 2222.08,2070.99 2254.19,2038.87 2263.39,2038.87 2272.58,2048.06 2272.58,2057.26 2240.46,2089.37 2240.46,2098.56 2249.66,2107.76 2258.85,2107.76 2290.96,2075.64 2300.16,2075.64 2309.35,2084.83 2309.35,2094.03 2280.01,2123.37 2280.01,2132.56 2282.13,2134.68 2289.36,2141.91 2358.82,2141.91 2362.36,2145.45 2382.87,2165.96 2392.06,2165.96 2410.83,2147.18 2420.03,2147.18 2429.22,2156.38 2429.22,2165.57 2407.53,2187.25 2407.53,2196.44 2416.73,2205.64 2425.92,2205.64 2447.6,2183.95 2456.79,2183.95 2465.99,2193.14 2465.99,2202.34 2444.3,2224.02 2444.3,2233.21 2453.5,2242.41 2462.69,2242.41 2484.37,2220.72 2493.56,2220.72 2502.76,2229.91 2502.76,2239.11 2483.98,2257.88 2483.98,2267.07 2496.36,2279.45 2505,2288.09 2505,2498.27 2573,2566.27 2573,2790.66 2619.58,2837.24 2619.58,2882.6 v1(2652.98,2916)
  Bottom Layer w8: v1(325.88,1621.47) v1(325.88,1621.47) 397.43,1621.53 J19.27@397.49,1621.6 ; v1(2523,3136.81) R221.1@2523,3160.76
TRACE_DATA5: J19.29 R228.1 | length 4589.3
  SIG1 w6: v1(459.31,1641.29) 488,1669.98 488,1699.54 488,1702.54 481.5,1709.04 457.15,1709.04 450.65,1715.54 450.65,1728.54 457.15,1735.04 486.09,1735.04 492.59,1741.54 492.59,1754.54 486.09,1761.04 457.15,1761.04 450.65,1767.54 450.65,1780.54 457.15,1787.04 486.09,1787.04 492.59,1793.54 492.59,1806.54 486.09,1813.04 457.15,1813.04 450.65,1819.54 450.65,1832.54 457.15,1839.04 481.5,1839.04 488,1845.54 488,1852.04 488,1928.7 555.3,1996 616.45,1996 735.69,2115.24 1130.97,2115.24 1182.39,2063.81 1415,2063.81 1450.62,2099.43 1553.96,2099.43 1560.39,2093 1702.77,2093 1732.77,2123 2054.21,2123 2235.79,2304.57 2235.79,2386.6 2290,2440.81 2290,2469.81 2296.5,2476.31 2320.98,2476.31 2327.48,2482.81 2327.48,2495.81 2320.98,2502.31 2293.75,2502.31 2287.25,2508.81 2287.25,2521.81 2293.75,2528.31 2320.98,2528.31 2327.48,2534.81 2327.48,2547.81 2320.98,2554.31 2293.75,2554.31 2287.25,2560.81 2287.25,2573.81 2293.75,2580.31 2320.98,2580.31 2327.48,2586.81 2327.48,2599.81 2320.98,2606.31 2293.75,2606.31 2287.25,2612.81 2287.25,2625.81 2293.75,2632.31 2320.98,2632.31 2327.48,2638.81 2327.48,2651.81 2320.98,2658.31 2293.75,2658.31 2287.25,2664.81 2287.25,2677.81 2293.75,2684.31 2320.98,2684.31 2327.48,2690.81 2327.48,2703.81 2320.98,2710.31 2293.75,2710.31 2287.25,2716.81 2287.25,2729.81 2293.75,2736.31 2320.98,2736.31 2327.48,2742.81 2327.48,2755.81 2320.98,2762.31 2296.5,2762.31 2290,2768.81 2290,2789.18 2290,2791.54 2290.57,2792.12 2311.08,2812.62 2320.27,2812.62 2336.25,2796.65 2345.44,2796.65 2354.63,2805.84 2354.63,2815.03 2335.69,2833.97 2335.69,2843.16 2344.89,2852.35 2354.08,2852.35 2373.02,2833.41 2382.21,2833.41 2391.4,2842.61 2391.4,2851.8 2372.46,2870.74 2372.46,2879.93 2381.66,2889.12 2390.85,2889.12 2409.79,2870.18 2418.98,2870.18 2428.17,2879.38 2428.17,2888.57 2409.23,2907.51 2409.23,2916.7 2418.43,2925.89 2427.62,2925.89 2446.56,2906.95 2455.75,2906.95 2464.94,2916.15 2464.94,2925.34 2448.97,2941.32 2448.97,2950.51 2461.63,2963.18 2469,2970.54 2469,2985 2479.91,2995.91 2502.15,2995.91 2513,3006.76 2513,3056.81 2522,3065.81 2566.16,3065.81 2596.16,3095.81 2606.52,3095.81 2635.52,3095.81 2642.02,3089.31 2642.02,3062.5 2648.52,3056 2661.52,3056 2668.02,3062.5 2668.02,3089.62 2674.52,3096.12 2687.52,3096.12 2694.02,3089.62 2694.02,3062.5 2700.52,3056 2713.52,3056 2720.02,3062.5 2720.02,3089.31 2726.52,3095.81 2738.83,3095.81 v1(2846,3095.81)
  Bottom Layer w8: J19.29@397.49,1641.29 v1@458.81,1641.29 ; v1(2846,3095.81) 2875,3124.81 R228.1@2875,3170.76
TRACE_DATA6: J19.31 R232.1 | length 4544.6
  SIG1 w6: v1(468.74,1680.66) 359.54,1680.66 345.43,1694.76 345.43,1850.69 349.28,1854.53 369.78,1875.04 378.98,1875.04 398.65,1855.37 407.84,1855.37 417.03,1864.56 417.03,1873.75 397.36,1893.43 397.36,1902.62 435.28,1940.53 622.98,2128.24 1139.56,2128.24 1159.64,2108.16 1420.1,2108.16 1449.3,2137.37 2046.09,2137.37 2218,2309.28 2218,2455.1 2218,2468.1 2214.57,2471.53 2214.57,2490.68 2218,2494.1 2262.06,2494.1 2268.56,2500.6 2268.56,2513.6 2262.06,2520.1 2218,2520.1 2214.57,2523.53 2214.57,2542.68 2218,2546.1 2262.06,2546.1 2268.56,2552.6 2268.56,2565.6 2262.06,2572.1 2218,2572.1 2214.57,2575.53 2214.57,2594.68 2218,2598.1 2262.06,2598.1 2268.56,2604.6 2268.56,2617.6 2262.06,2624.1 2218,2624.1 2214.57,2627.53 2214.57,2646.68 2218,2650.1 2262.06,2650.1 2268.56,2656.6 2268.56,2669.6 2262.06,2676.1 2224.5,2676.1 2218,2682.6 2218,2684 2218,2837.81 2238.61,2858.42 2259.12,2878.93 2268.31,2878.93 2296.39,2850.84 2305.58,2850.84 2314.78,2860.04 2314.78,2869.23 2283.53,2900.47 2283.53,2909.66 2292.73,2918.86 2301.92,2918.86 2333.16,2887.61 2342.35,2887.61 2351.55,2896.81 2351.55,2906 2320.3,2937.24 2320.3,2946.43 2329.5,2955.62 2338.69,2955.62 2369.93,2924.38 2379.12,2924.38 2388.32,2933.57 2388.32,2942.77 2357.07,2974.01 2357.07,2983.2 2366.27,2992.39 2375.46,2992.39 2406.7,2961.15 2415.89,2961.15 2425.09,2970.34 2425.09,2979.54 2393.84,3010.78 2393.84,3019.97 2403.04,3029.16 2412.23,3029.16 2443.47,2997.92 2452.66,2997.92 2461.85,3007.11 2461.85,3016.31 2433.77,3044.39 2433.77,3053.58 2447.75,3067.56 2458,3077.81 2553,3077.81 2599,3123.81 v1(2689,3123.81)
  Bottom Layer w8: J19.31@397.49,1660.97 449.06,1660.97 v1(468.74,1680.66) ; R232.1@2686,3170.76 2687.5,3169.26 2687.5,3125.31 v1(2689,3123.81)
TRACE_DATA7: J19.33 R236.1 | length 4466.3
  SIG1 w6: v1@326.24,1679.86 326.24,1848.47 629.93,2152.16 1140.34,2152.16 1166.5,2126 1375.55,2126 1401.36,2151.81 2038.89,2151.81 2200,2312.92 2200,2326 2200,2329 2193.5,2335.5 2158.24,2335.5 2151.74,2342 2151.74,2355 2158.24,2361.5 2197.07,2361.5 2203.57,2368 2203.57,2381 2197.07,2387.5 2158.24,2387.5 2151.74,2394 2151.74,2407 2158.24,2413.5 2197.07,2413.5 2203.57,2420 2203.57,2433 2197.07,2439.5 2158.24,2439.5 2151.74,2446 2151.74,2459 2158.24,2465.5 2196.07,2465.5 2202.57,2472 2202.57,2485 2196.07,2491.5 2158.24,2491.5 2151.74,2498 2151.74,2511 2158.24,2517.5 2196.07,2517.5 2202.57,2524 2202.57,2537 2196.07,2543.5 2158.24,2543.5 2151.74,2550 2151.74,2563 2158.24,2569.5 2196.07,2569.5 2202.57,2576 2202.57,2589 2196.07,2595.5 2158.24,2595.5 2151.74,2602 2151.74,2615 2158.24,2621.5 2196.07,2621.5 2202.57,2628 2202.57,2641 2196.07,2647.5 2158.24,2647.5 2151.74,2654 2151.74,2667 2158.24,2673.5 2197.07,2673.5 2203.57,2680 2203.57,2693 2197.07,2699.5 2158.24,2699.5 2151.74,2706 2151.74,2719 2158.24,2725.5 2197.07,2725.5 2203.57,2732 2203.57,2745 2197.07,2751.5 2158.24,2751.5 2151.74,2758 2151.74,2771 2158.24,2777.5 2193.5,2777.5 2200,2784 2200,2793.47 2200,2888.39 2214.21,2902.6 2218.81,2907.2 2218.81,2916.39 2199.79,2935.4 2199.79,2944.6 2208.98,2953.79 2218.18,2953.79 2241.79,2930.18 2248.26,2930.18 2260.17,2942.09 2260.17,2948.56 2238.87,2969.86 2238.87,2979.06 2248.06,2988.25 2257.26,2988.25 2278.56,2966.95 2285.03,2966.95 2296.94,2978.86 2296.94,2985.33 2275.64,3006.63 2275.64,3015.83 2284.83,3025.02 2294.02,3025.02 2315.33,3003.72 2321.8,3003.72 2333.71,3015.63 2333.71,3022.1 2310.1,3045.71 2310.1,3054.91 2319.29,3064.1 2328.48,3064.1 2352.1,3040.49 2357.22,3040.49 2370.48,3053.74 2370.48,3058.87 2379.71,3068.1 2408.61,3097 2483.55,3097 2487.25,3093.3 2533,3093.3 v1(2551,3111.3)
  Bottom Layer w8: v1(326.25,1679.86) 326.65,1680.26 397.09,1680.26 J19.33@397.49,1680.66 ; v1(2551,3111.3) R236.1@2551,3160.76
TRD1_N: D18.1 L7.1 R260.1 R265.2 | length 198.7
  Bottom Layer w4.8: L7.1@1274.27,3589.95 1283.68,3580.54 1294.98,3580.54 1300.15,3575.36 1313.06,3575.36 1315.88,3578.17 1315.88,3584.37 1320.25,3588.75 D18.1@1322.29,3588.75 1326.52,3588.75 1339.46,3575.81 1383.93,3575.81 1394.52,3586.4 R265.2@1396.49,3586.4 1384.23,3598.67 1378.13,3598.67 R260.1@1358.29,3618.51
TRD1_P: D19.1 L7.2 R270.2 R274.2 | length 199.5
  Bottom Layer w4.8: L7.2@1274.27,3550.58 1283.68,3559.99 1294.98,3559.99 1300.15,3565.16 1313.06,3565.16 1315.88,3562.35 1315.88,3556.15 1320.25,3551.78 D19.1@1322.29,3551.78 1326.38,3551.78 1330.75,3556.15 1330.75,3556.21 1340.16,3565.61 1383.04,3565.61 1394.52,3554.12 R270.2@1396.49,3554.12 1384.23,3541.86 1378.13,3541.86 R274.2@1358.29,3522.02
TRD2_N: C157.2 L7.4 | length 121.1
  Bottom Layer w4.8: C157.2@1077.67,3615.54 1077.67,3578.17 1080.48,3575.36 1099.29,3575.36 1128.31,3575.36 1133.48,3580.54 1144.78,3580.54 L7.4@1154.19,3589.95
TRD2_P: C161.2 L7.3 | length 121.1
  Bottom Layer w4.8: C161.2@1077.67,3524.99 1077.67,3562.35 1080.48,3565.16 1103.52,3565.16 1128.31,3565.16 1133.48,3559.99 1144.78,3559.99 L7.3@1154.19,3550.58
TRD3_N: C157.1 D15.1 J4.2 R281.2 | length 430.2
  Top Layer w4.8: R281.2@663.7,3615.44 663.7,3609.53 697.77,3575.46 729.97,3575.46 758.25,3603.74 J4.2@758.25,3605.69
  Bottom Layer w4.8: J4.2@758.25,3605.69 788.05,3575.9 855.78,3575.9 869.67,3589.78 877.86,3589.78 892.28,3575.36 936.59,3575.36 994.86,3575.36 997.67,3578.17 C157.1@997.67,3615.54
TRD3_P: C161.1 D17.1 J4.1 R275.2 | length 434.1
  Top Layer w4.8: R275.2@663.7,3525.09 663.7,3530.99 697.97,3565.26 732.07,3565.26 755.81,3541.52 758.25,3541.52 J4.1@758.25,3534.83
  Bottom Layer w4.8: J4.1@758.25,3534.83 789.12,3565.7 854.71,3565.7 869.67,3550.74 D17.1@873.77,3550.74 877.86,3550.74 883.18,3556.06 892.28,3565.16 936.59,3565.16 994.86,3565.16 997.67,3562.35 C161.1@997.67,3524.99
TX0_N: J7.58 R366.1 | length 101.3
  Top Layer w4.8: J7.58@623.08,662.86 626.18,665.95 671.38,665.95 673.03,667.6 709.92,667.6 712.73,664.79 712.73,662.6 716.63,658.7 R366.1@717.41,658.7
TX0_P: J7.56 R365.1 | length 101.3
  Top Layer w4.8: J7.56@623.08,682.55 626.18,679.45 671.38,679.45 673.03,677.8 709.92,677.8 712.73,680.62 712.73,682.81 716.63,686.7 R365.1@717.41,686.7
TX1_N: J7.52 R364.1 | length 101.3
  Top Layer w4.8: J7.52@623.08,721.92 626.18,725.01 671.38,725.01 673.03,726.66 709.92,726.66 712.73,723.85 712.73,721.66 716.63,717.76 R364.1@717.41,717.76
TX1_P: J7.50 R363.1 | length 101.3
  Top Layer w4.8: J7.50@623.08,741.6 626.18,738.51 671.38,738.51 673.03,736.86 709.92,736.86 712.73,739.67 712.73,741.86 716.63,745.76 R363.1@717.41,745.76
TX2_CLK_N: J7.46 R361.1 | length 327.5
  Top Layer w4.8: J7.46@623.08,780.97 626.18,784.06 671.38,784.06 673.03,785.71 733.23,785.71 747.2,799.69 747.2,861.99 750.01,864.8 771.37,864.8 774.8,861.37 774.8,799.15 788.07,785.88 800.17,785.88 806.71,779.34 R361.1@807.5,779.34
TX2_CLK_P: J7.44 R351.1 | length 332.1
  Top Layer w4.8: J7.44@623.08,800.66 626.18,797.57 671.38,797.57 673.03,795.91 729,795.91 737,803.91 737,866.21 745.79,875 775.59,875 785,865.59 785,803.37 792.29,796.08 800,796.08 802.81,798.89 802.81,803.44 806.71,807.34 R351.1@807.5,807.34
TX2_N: J7.40 R349.1 | length 302.8
  Top Layer w4.8: J7.40@623.08,840.03 626.18,843.12 671.38,843.12 673.03,844.77 705,844.77 713.97,835.8 v1(717.5,835.8)
  Bottom Layer w4.8: v1(717.5,835.8) 717.5,836.28 732.63,851.42 757.15,851.42 770.93,865.19 781.39,865.19 791,855.58 791,844.42 763.92,817.34 763.92,795.2 772.71,786.41 787.19,786.41 796.71,776.9 R349.1@797.5,776.9
TX2_P: J7.38 R345.1 | length 296.4
  Top Layer w4.8: J7.38@623.08,859.71 626.18,856.62 671.38,856.62 673.03,854.97 705,854.97 713.9,863.87 v1(717.41,863.87)
  Bottom Layer w4.8: v1(717.41,863.87) 719.67,861.62 752.93,861.62 766.71,875.39 785.61,875.39 801.2,859.8 801.2,840.2 774.12,813.12 774.12,799.42 776.93,796.61 788.43,796.61 796.71,804.9 R345.1@797.5,804.9
TX3_FRCLK_N: J7.28 R323.1 | length 319.1
  Top Layer w4.8: J7.28@623.08,958.14 626.18,961.23 671.38,961.23 673.03,962.88 695.07,962.88 695.13,962.82 708.08,962.82 717,953.91 v1(717.5,953.91)
  Bottom Layer w4.8: v1(717.5,953.91) 717.97,953.91 726.91,962.84 743.08,962.84 748.56,957.36 748.56,941.51 742.99,935.94 726.45,935.94 714.6,924.09 714.6,905.88 726.37,894.11 769.08,894.11 778.84,903.87 800,903.87 802.81,901.05 802.81,898.9 806.71,895.01 R323.1@807.5,895.01
TX3_FRCLK_P: J7.26 R322.1 | length 319
  Top Layer w4.8: J7.26@623.08,977.82 626.18,974.73 671.38,974.73 673.03,973.08 700.14,973.08 700.2,973.02 708,973.02 716.96,981.98 v1(717.41,981.98)
  Bottom Layer w4.8: v1(717.41,981.98) 717.89,981.98 726.83,973.04 747.3,973.04 758.76,961.59 758.76,937.29 747.22,925.74 730.67,925.74 724.8,919.87 724.8,910.11 730.6,904.31 764.86,904.31 774.61,914.07 799.92,914.07 802.73,916.88 802.73,919.03 806.63,922.93 R322.1@807.41,922.93
TX3_N: J7.34 R341.1 | length 314.5
  Top Layer w4.8: J7.34@623.08,899.08 626.18,902.17 671.38,902.17 673.03,903.83 734,903.83 750.6,920.42 750.6,971.23 755.88,976.51 769.7,976.51 775.06,971.15 775.06,912.31 784.91,902.46 799.25,902.46 806.71,895.01 R341.1@807.5,895.01
TX3_P: J7.32 R327.1 | length 316.8
  Top Layer w4.8: J7.32@623.08,918.77 626.18,915.68 671.38,915.68 673.03,914.03 729.78,914.03 740.4,924.65 740.4,975.46 751.65,986.71 773.92,986.71 785.26,975.38 785.26,916.54 789.13,912.66 798.52,912.66 802.73,916.88 802.73,919.03 806.63,922.93 R327.1@807.41,922.93
TX_CTRL: R101.2 U15.37 | length 3524.4
  Top Layer w8: U15.37@1284.77,2700.12 1305.97,2700.12 1353.08,2747.23 1353.08,2772.89 1371,2790.81 1396.66,2790.81 1411.72,2805.87 v1(1471.02,2805.87)
  SIG2 w6: v1(1471.02,2805.87) 1492.91,2783.98 1503.7,2783.98 1532.7,2783.98 1539.2,2777.48 1539.2,2744.26 1545.7,2737.76 1558.7,2737.76 1565.2,2744.26 1565.2,2783.36 1571.7,2789.86 1584.7,2789.86 1591.2,2783.36 1591.2,2744.26 1597.7,2737.76 1610.7,2737.76 1617.2,2744.26 1617.2,2777.48 1623.7,2783.98 1646.97,2783.98 1690.41,2783.98 1734.44,2828.01 1734.44,2853.81 1734.44,2856.81 1727.94,2863.31 1700.24,2863.31 1693.74,2869.81 1693.74,2882.81 1700.24,2889.31 1734.06,2889.31 1740.56,2895.81 1740.56,2908.81 1734.06,2915.31 1700.24,2915.31 1693.74,2921.81 1693.74,2934.81 1700.24,2941.31 1734.06,2941.31 1740.56,2947.81 1740.56,2960.81 1734.06,2967.31 1700.24,2967.31 1693.74,2973.81 1693.74,2986.81 1700.24,2993.31 1734.06,2993.31 1740.56,2999.81 1740.56,3012.81 1734.06,3019.31 1700.24,3019.31 1693.74,3025.81 1693.74,3038.81 1700.24,3045.31 1727.94,3045.31 1734.44,3051.81 1734.44,3075.81 1734.44,3127.86 1429.94,3432.36 1429.94,3802.29 1599,3971.35 1599,4089.13 1980.68,4470.81 2066.87,4470.81 2104.87,4432.81 2279.88,4432.81 2295.89,4448.83 v1(2454.4,4448.83)
  Bottom Layer w8: v1(2454.4,4448.83) R101.2@2454.42,4476.69
UART_RX_FTDI: R160.1 U18.38 | length 127.9
  Bottom Layer w8: U18.38@1332.18,4358.9 1447.75,4358.9 R160.1@1456.49,4350.15
UART_TX_FTDI: R131.2 R164.1 U18.39 | length 6999
  SIG2 w6: v1(1440.62,4277.86) 1440.62,3903.68 921.28,3384.34 921.28,3037.3 1052.65,2905.93 1052.65,2871.24 832.52,2651.11 832.52,2444.92 808,2420.4 808,2201.84 717.68,2111.52 632.76,2111.52 492.29,1971.05 492.29,1726.95 531.27,1687.96 531.27,1261.93 614,1179.2 614,603.81 569.53,559.34 569.53,448.27 580.54,437.26 606.45,437.26 617,447.81 645,447.81 661.81,431 939.4,431 956.21,447.81 1101,447.81 1258.73,605.54 1598.08,605.54 1696.29,507.33 2178.52,507.33 2414.66,743.48 2414.66,1011.12 2408,1017.78 v1(2408,1020.63)
  Bottom Layer w8: U18.39@1332.18,4339.21 1418.39,4339.21 R164.1@1456.49,4301.11 ; v1(1440.62,4277.86) 1441.43,4278.68 1453.54,4278.68 1459.3,4284.43 R164.1@1459.3,4298.31 ; v1(2408,1020.63) R131.2@2430.04,1020.63
V3V3_PHY: C55.2 C196.1 R51.1 U4.7 U33.6 | length 604.4
  Top Layer w20: C196.1@763.1,3251.92 773.57,3262.39 865.27,3262.39 890,3237.66 1087.08,3237.66 1124.4,3274.98 1162.16,3274.98 v1(1182.57,3254.57)
  Bottom Layer w10: R51.1@1182.57,3187.4 1183.04,3186.94 U4.7@1262.03,3186.94
  Bottom Layer w15: R51.1@1182.57,3187.4 C55.2@1182.57,3222.97 v1@1182.57,3254.17
VBAT_INT: C80.1 C99.1 C101.1 C118.2 C173.2 C195.1 C197.1 L5.2 R7.1 R52.2 R250.2 R331.2 U2.12 U5.10 U33.1 | length 6647.6
  Top Layer w10: R52.2@276.53,458.31 v1(311.32,458.31)
  Top Layer w15: R250.2@531.97,3247.26 531.97,3310.59 v1(542.32,3320.94) C197.1@576.83,3320.94 589.98,3320.94 590.65,3321.61 v1(590.65,3383.17)
  PWR1 w20: v1(542.32,3320.94) 542.32,3083.13 455,2995.81 455,2942.81 511.15,2886.66 v1(550.72,2886.66) 624.15,2886.66 724,2786.81 724,2243.09 513.72,2032.81 172,2032.81 54,1914.81 54,517.81 113.5,458.31 v1(311.32,458.31) 322.69,458.31 436.19,344.81 817.62,344.81 v1(859.95,302.49)
  PWR1 w30: v1(859.95,302.49) 898.76,263.68 898.76,98.05 940,56.81 2151.28,56.81 2192,97.53 2192,405.22 2168.3,428.92 v1(2139.54,428.92)
  Bottom Layer w10: U5.10@825.99,385.8 C80.1@825.99,298.55 v1@856.01,298.55
  other v1: 2238.45,419.17 2340.29,419.17 2442.12,419.17 2057.7,428.92 2098.62,428.92 2238.45,460.09 2340.29,460.09 2442.12,460.09 2057.7,469.84 2098.62,469.84 2139.54,469.84 2238.45,501.01 2340.29,501.01 2442.12,501.01
VBGAP: C180.1 U29.J1 | length 86.7
  Top Layer w12: C180.1@2178.59,3898.25 v1(2217.96,3898.25)
  Bottom Layer w4: v1(2217.96,3898.25) 2218.62,3898.25 U29.J1@2265.3,3898.25
VBUS_1_DETECT: C109.2 R284.1 R285.2 U6.1 | length 161.5
  Bottom Layer w8: 2755.58,1065.5 U6.1@2755.58,1104.01
  Bottom Layer w10: 2755.58,1072.61 R285.2@2755.58,1022 C109.2@2791.65,1022 R284.1@2828,1022
VDDC_1: C62.1 C64.2 C74.2 C75.2 U6.87 U6.115 | length 1020.6
  PWR1 w20: v1(2550.86,1780.22) 2550.86,1671.95 2840,1382.81 2840,1327.98 v1(2895.17,1272.81)
  Bottom Layer w6: U6.87@2613.85,1710.31 2613.85,1757.73
  Bottom Layer w7: U6.115@2814.64,1367.79 2855.17,1367.79
  Bottom Layer w10: v1(2550.86,1780.22) C74.2@2550.86,1807.73 C75.2@2590.64,1807.73 2590.64,1780.94 2613.85,1757.73 ; 2855.26,1367.88 2866.46,1367.88 2882.81,1351.53 2882.81,1326.73 2892.55,1316.99 2912.17,1316.99 C64.2@2913.5,1315.66 C62.1@2913.5,1272.74 2913.43,1272.81 v1(2895.17,1272.81)
VDDIO_ETH: C53.1 C158.1 C183.1 C184.1 C185.1 C186.1 R92.2 R108.2 R112.2 R132.2 R139.2 R141.2 R173.2 R211.2 R286.2 R295.1 R340.2 R342.2 U15.19 U15.30 U15.41 U16.4 | length 1499.4
  Top Layer w8: U15.19@1185.77,2431.68 1185.77,2418 1195.97,2407.8 ; U15.41@1205.46,2699.4 1205.46,2723.36 ; U15.30@1309.79,2555.7 1330,2555.7
  Top Layer w10: R108.2@552.17,3047.15 552.17,2997.37 R112.2@538.39,2983.59 540.45,2981.53 562.24,2981.53 v1(563.77,2980) ; U16.4@806.17,3066.73 827.64,3066.73 895.03,2999.34 R295.1@918.99,2999.34 ; v1(1189.76,2800.53) 1219.22,2800.53 C185.1@1223.15,2804.47 1223.15,2800.53 1223.15,2777.86 1205.46,2760.16 1205.46,2723.36 ; 1195.97,2407.8 1220.92,2382.85 v1(1220.92,2382.45) ; R141.2@1198.68,2975.21 1238.01,2975.21 1334.56,2878.66 R211.2@1471.91,2878.66 ; C184.1@1220.92,2332.83 v1@1220.92,2378.08 ; 1330,2555.7 1373.66,2555.7 1392.53,2536.83 C158.1@1414.49,2536.83 ; C158.1@1410.55,2536.83 v1(1410.55,2567.69)
  Bottom Layer w10: v1(563.77,2980) 586.87,3003.1 995.3,3003.1 1008.08,2990.32 v1(1008.08,2975.95) ; v1(1189.76,2800.53) 1197.63,2792.66 C53.1@1223.15,2792.66 ; C186.1@1403.08,2531.54 1410.55,2539.01 v1(1410.55,2567.69)
  other v1: 1008.08,2997.52
VDDIO_ETH2: C32.1 C35.1 C36.2 R28.2 R34.1 R46.1 R252.2 R253.2 R254.2 R255.2 R256.2 R257.2 R258.2 U4.34 | length 442.8
  Top Layer w8: R252.2@1401.29,3383.67 v1(1401.29,3412.15) ; R258.2@1653.64,3200.99 1689.26,3200.99 v1(1689.45,3201.18)
  Top Layer w8.3: v1(1113.52,3053.97) 1113.52,3059.31 R46.1@1143.2,3088.99
  Top Layer w10: R254.2@1474.75,3383.67 v1(1474.75,3412.15) ; R255.2@1653.64,3056.06 1653.64,3103.94 1653.64,3151.97 R258.2@1653.64,3200.99
  Top Layer w15: C36.2@1297.46,3038.39 C35.1@1336.83,3038.39 v1(1336.83,3007.39)
  Bottom Layer w8: v1(1113.52,3053.97) 1115.27,3052.21 R34.1@1143.2,3052.21 ; v1(1401.29,3412.15) 1407.02,3406.42 R253.2@1407.02,3383.59
  Bottom Layer w10: v1(1336.83,3007.39) U4.34@1336.83,3033.39
  other v1: 980.52,3043.11 1005.4,3043.11 1030.46,3043.11 1005.4,3068.16
VLDO_3V3: C93.1 C94.1 R182.1 R202.2 U20.3 U20.4 | length 343.4
  Bottom Layer w10: C94.1@1590.78,4668.86 1590.78,4700.64 1611.51,4721.37 1758.38,4721.37 1800.03,4679.72 R202.2@1800.03,4603.23
VPHY_FTDI: C68.1 C69.2 L3.2 U18.4 | length 366.6
  Top Layer w15: C68.1@772.94,4221.1 v1(813.55,4221.1)
  Bottom Layer w10: v1(813.55,4221.1) U18.4@895.17,4221.1
  Bottom Layer w15: L3.2@607.41,4221.1 637.27,4191.24 758.26,4191.24 765.07,4198.05 765.07,4221.1 v1(813.55,4221.1)
VPLL_FTDI: C72.1 C73.2 L4.2 U18.9 | length 371.7
  Top Layer w15: C72.1@769,4319.53 v1(813.55,4319.53)
  Bottom Layer w10: v1(813.55,4319.53) U18.9@895.17,4319.53
  Bottom Layer w15: L4.2@608.16,4319.53 641.1,4352.47 754,4352.47 765.07,4341.41 765.07,4319.53 v1(813.55,4319.53)
VPP_1P7: C150.2 P1.1 U29.U6 | length 2561.1
  PWR1 w20: v1(2283.54,4328) v1(2283.54,4498.25)
  PWR2 w20: P1.1@552.17,4632.33 749.84,4830 2234.81,4830 2283.22,4781.6 v1@2283.22,4498.31
  Bottom Layer w7: 2351.52,4207.62 2371.73,4187.41 2371.73,4166.15 2384.28,4153.6 2384.28,4129.18 2393.13,4120.33 2393.13,4103.1 U29.U6@2393.25,4102.97
  Bottom Layer w15: v1(2283.54,4328) 2283.54,4327.19 2304.59,4306.13 C150.2@2304.59,4253 2306.56,4253 2308.91,4250.66 2308.91,4245.22 2346.51,4207.62 2351.52,4207.62
VPP_EN: R159.1 U29.U3 | length 3045.6
  Top Layer w8: R159.1@323.96,4737.7 v1(323.96,4772.2)
  SIG2 w6: v1(323.96,4772.2) 346.15,4750 553.95,4750 579.95,4776 1612,4776 1626,4762 1975,4762 1999,4786 2160.31,4786 2244.31,4702 2436.67,4702 2456.96,4681.71 v1(2456.96,4674)
  Bottom Layer w4: 2199.24,4274 2199.24,4255.48 2316.48,4138.24 U29.U3@2316.48,4102.97
  Bottom Layer w8: 2199.24,4274 2199.24,4293 2256.24,4350 2302.97,4350 2344.66,4391.69 2344.66,4561.7 2363.22,4580.26 2427.72,4580.26 2456.96,4609.5 v1(2456.96,4674)
WRMRST_FTDI: R330.1 U18.46 | length 144.7
  Bottom Layer w8: U18.46@1332.18,4201.42 1407.28,4201.42 R330.1@1456.51,4152.19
